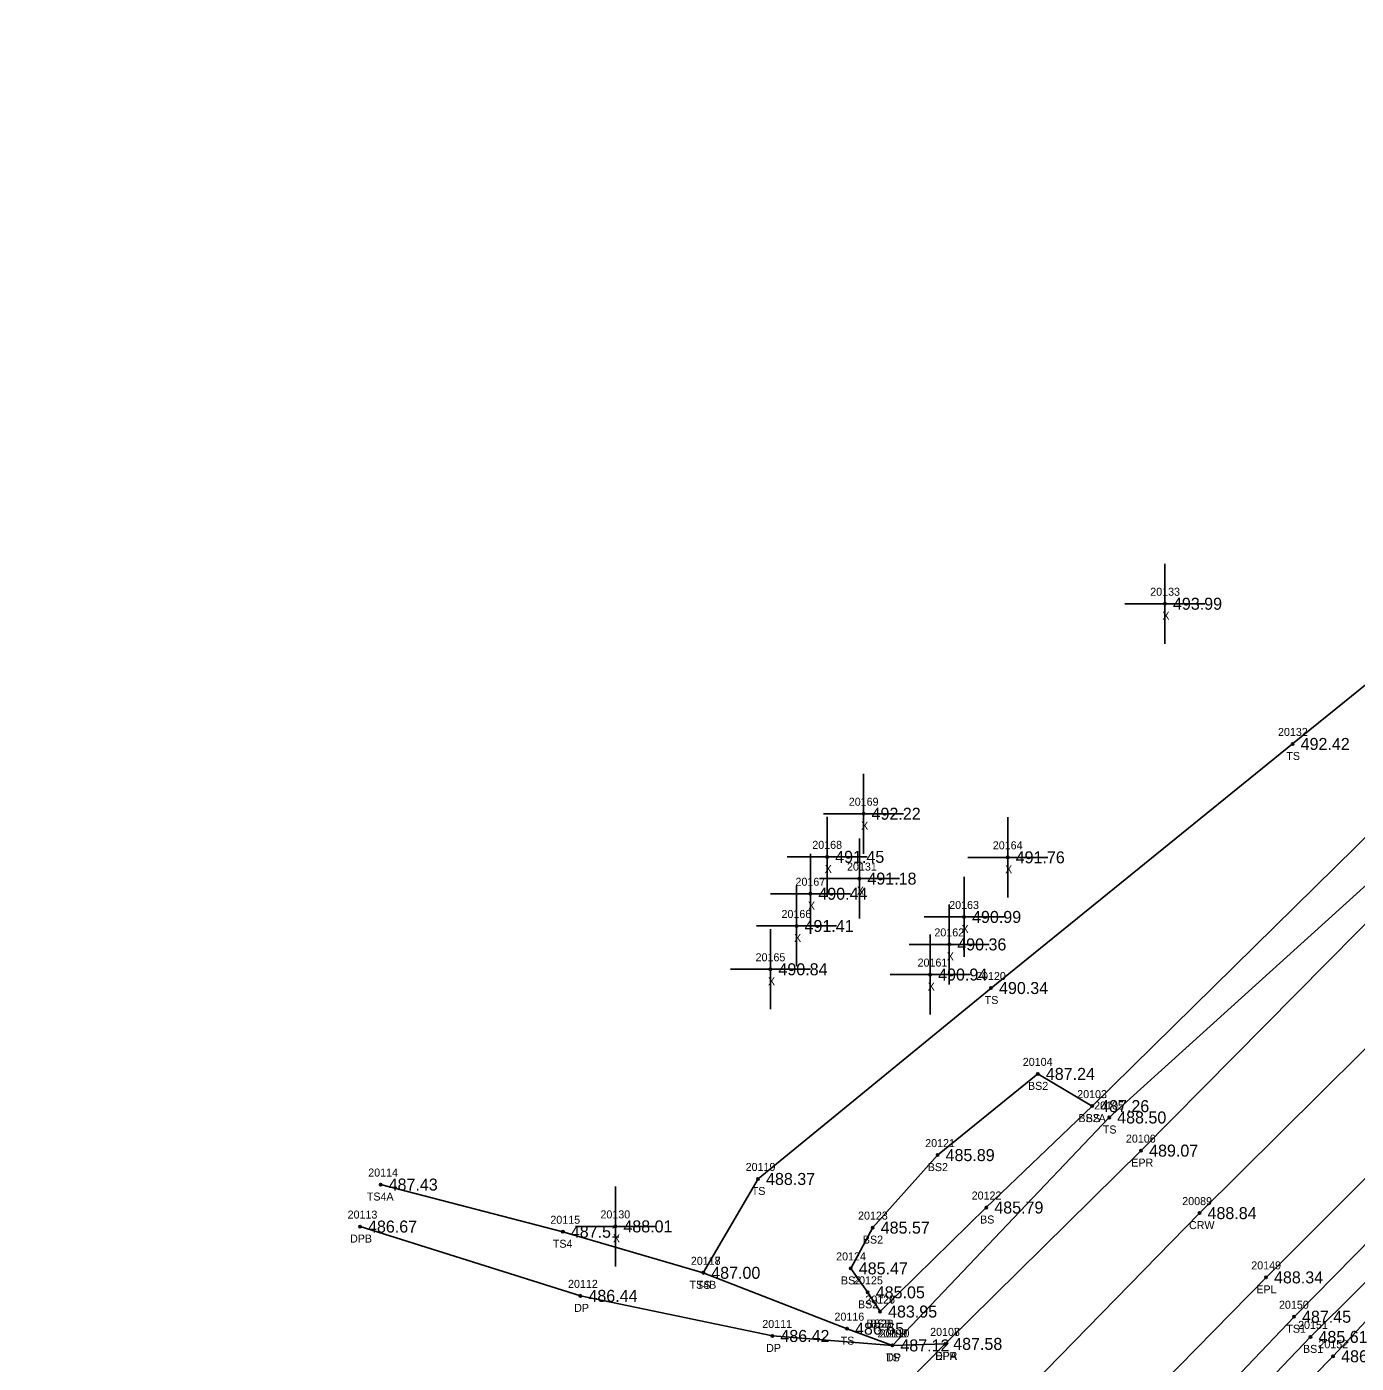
# Model space of a CAD drawing. Extents: x 1741010 to 1742139, y 749382 to 750625.
# Drawn here: x 1741801.4 to 1741967.6, y 750426.2 to 750593.3 of the extents above; entities that cross this region are included whole.
import ezdxf

# ---------------------------------------------------------------- set-up
doc = ezdxf.new("R2010")
doc.units = 0
for name, color, linetype in [('RD_DTM_BkLn1', 7, 'Continuous'), ('RD_DTM_BkLn2', 7, 'Continuous'), ('RD_DTM_BkLn_txCode', 7, 'Continuous'), ('RD_EX_Driveway', 7, 'Continuous'), ('RD_EX_Driveway_txCode', 7, 'Continuous'), ('RD_EX_Misc', 7, 'Continuous'), ('RD_EX_Misc_txCode', 7, 'Continuous'), ('RD_EX_Road', 7, 'Continuous'), ('RD_EX_Road_txCode', 7, 'Continuous'), ('RD_EX_TX_Driveway_ELEV', 7, 'Continuous'), ('RD_EX_TX_Misc_ELEV', 7, 'Continuous'), ('RD_EX_TX_Road_ELEV', 7, 'Continuous'), ('RD_HC_Survey_ELEV', 7, 'Continuous'), ('RD_HC_Survey_txCode', 7, 'Continuous'), ('RD_SMD_Locator', 7, 'Continuous')]:
    doc.layers.add(name, color=color, linetype=linetype)

msp = doc.modelspace()

# ---------------------------------------------------------------- linework, layer by layer
at = {"layer": 'RD_DTM_BkLn1'}
msp.add_lwpolyline([(1742095.1, 750579.47), (1742056.96, 750547.11), (1742019.74, 750514.22), (1741983.45, 750480.17), (1741948.01, 750445.01), (1741913.15, 750409.3), (1741879.03, 750372.99), (1741811.59, 750300.09), (1741743.65, 750226.52), (1741676.29, 750153.06), (1741642.32, 750115.53), (1741610.32, 750077.63)], dxfattribs=at)
at = {"layer": 'RD_DTM_BkLn2'}
for points in [[(1742105.6, 750567.48), (1742094.25, 750560.49), (1742091.64, 750555.7), (1742067.93, 750534.94), (1742031.73, 750501.95), (1741994.85, 750467.63), (1741959.82, 750432.06), (1741925.8, 750396.31), (1741891.25, 750362.62), (1741824.36, 750287.7), (1741756.44, 750214.6), (1741688.69, 750142.04), (1741655.55, 750103.43), (1741644.64, 750083.31), (1741626.06, 750060.3), (1741620, 750055.3), (1741614.97, 750059.12), (1741617.5, 750064.27), (1741619.23, 750067.96)], [(1742107.37, 750564.98), (1742099.21, 750558.66), (1742095.99, 750559.5), (1742095.15, 750554.39), (1742069.73, 750532.61), (1742034.06, 750499.81), (1741997.6, 750464.99), (1741961.88, 750429.54), (1741928.13, 750394.17), (1741895.34, 750359.02), (1741826.5, 750286.36), (1741758.73, 750213.29), (1741690.1, 750140.59), (1741658.36, 750099.77), (1741650.43, 750077.87), (1741632.9, 750061.59), (1741621.97, 750051.56), (1741618.99, 750048.78), (1741611.88, 750047.79)], [(1742108.6, 750563.87), (1742101.48, 750556.48), (1742102.57, 750548.5), (1742101.05, 750532.99), (1742105.06, 750513.92), (1742103.27, 750510.53), (1742100.54, 750509.6), (1742099.13, 750514.58), (1742095.78, 750530.6), (1742094.19, 750550.08), (1742071, 750531.59), (1742035.26, 750498.87), (1741998.91, 750463.73), (1741964.71, 750427.12), (1741930.26, 750392.09), (1741896.36, 750357.96), (1741828.15, 750284.74), (1741760.22, 750211.9), (1741691.37, 750138.81), (1741661.95, 750096.11), (1741655.14, 750072.69), (1741637.21, 750056.01), (1741627.61, 750046.43), (1741623.09, 750045.5)], [(1742037.14, 750559.31), (1742007.02, 750528.39), (1741970.04, 750493.22), (1741934.59, 750458.38), (1741921.36, 750445.71), (1741908.08, 750432.71)], [(1742045.12, 750555.47), (1742011.8, 750524.29), (1741973.5, 750489.25), (1741973.31, 750490.05), (1741936.72, 750456.96), (1741909.62, 750428.48), (1741903.95, 750430.57), (1741885.98, 750437.55), (1741892.83, 750449.28), (1741921.95, 750473.14), (1741959.65, 750503.64), (1742000.15, 750536.41)], [(1741934.59, 750458.38), (1741927.8, 750462.41), (1741915.27, 750452.26), (1741907.16, 750443.2), (1741904.42, 750438.1), (1741906.54, 750435.11), (1741908.08, 750432.71)], [(1741845.66, 750448.58), (1741868.43, 750442.68), (1741885.98, 750437.55)]]:
    msp.add_lwpolyline(points, dxfattribs=at)
at = {"layer": 'RD_EX_Driveway'}
msp.add_lwpolyline([(1741916.22, 750428.67), (1741909.62, 750428.48), (1741894.62, 750429.66), (1741870.63, 750434.67), (1741843.08, 750443.33)], dxfattribs=at)
at = {"layer": 'RD_EX_Misc'}
for p, q in [((1741943.69, 750516.16), (1741943.69, 750526.16)), ((1741938.69, 750521.16), (1741948.69, 750521.16)), ((1741906.02, 750489.92), (1741906.02, 750499.92)), ((1741901.02, 750494.92), (1741911.02, 750494.92)), ((1741901.47, 750484.53), (1741901.47, 750494.53)), ((1741924.03, 750484.47), (1741924.03, 750494.47)), ((1741905.5, 750481.81), (1741905.5, 750491.81)), ((1741899.37, 750479.92), (1741899.37, 750489.92)), ((1741896.47, 750489.53), (1741906.47, 750489.53)), ((1741919.03, 750489.47), (1741929.03, 750489.47)), ((1741900.5, 750486.81), (1741910.5, 750486.81)), ((1741918.58, 750477.02), (1741918.58, 750487.02)), ((1741894.37, 750484.92), (1741904.37, 750484.92)), ((1741897.64, 750475.89), (1741897.64, 750485.89)), ((1741916.73, 750473.59), (1741916.73, 750483.59)), ((1741913.58, 750482.02), (1741923.58, 750482.02)), ((1741892.64, 750480.89), (1741902.64, 750480.89)), ((1741894.38, 750470.48), (1741894.38, 750480.48)), ((1741914.34, 750469.82), (1741914.34, 750479.82)), ((1741911.73, 750478.59), (1741921.73, 750478.59)), ((1741889.38, 750475.48), (1741899.38, 750475.48)), ((1741909.34, 750474.82), (1741919.34, 750474.82)), ((1741875, 750438.35), (1741875, 750448.35)), ((1741870, 750443.35), (1741880, 750443.35))]:
    msp.add_line(p, q, dxfattribs=at)
at = {"layer": 'RD_EX_Road'}
for points in [[(1742095.24, 750593.27), (1742088.27, 750587.97), (1742078.23, 750580.89), (1742049.13, 750555.21), (1742012.94, 750522.73), (1741975.54, 750488.03), (1741940.71, 750452.82), (1741916.22, 750428.67), (1741904.72, 750416.99), (1741884.38, 750395.02), (1741870.75, 750380.27), (1741817.36, 750322.98), (1741803.89, 750307.66), (1741783.86, 750287.33), (1741735.44, 750234.07), (1741718.84, 750214.98), (1741710.25, 750205.58), (1741668.97, 750159.8), (1741635, 750122.49), (1741604.35, 750087.7), (1741600.63, 750085.47)], [(1742102.43, 750570.61), (1742093.26, 750562.71), (1742064.72, 750538.42), (1742027.92, 750505.65), (1741991.25, 750471.83), (1741956.32, 750436.98), (1741921.43, 750401.39), (1741886.79, 750364.93), (1741819.64, 750292.67), (1741751.78, 750219.01), (1741684.42, 750145.59), (1741650.98, 750108.5), (1741637.17, 750092.42), (1741621.17, 750073.94), (1741621.31, 750072.22), (1741619.24, 750070.27)]]:
    msp.add_lwpolyline(points, dxfattribs=at)
at = {"layer": 'RD_SMD_Locator'}
for centre in [(1741943.69, 750521.16), (1741959.65, 750503.64), (1741906.02, 750494.92), (1741901.47, 750489.53), (1741924.03, 750489.47), (1741905.5, 750486.81), (1741899.37, 750484.92), (1741918.58, 750482.02), (1741897.64, 750480.89), (1741916.73, 750478.59), (1741894.38, 750475.48), (1741914.34, 750474.82), (1741921.95, 750473.14), (1741927.8, 750462.41), (1741934.59, 750458.38), (1741934.59, 750458.38), (1741936.72, 750456.96), (1741940.71, 750452.82), (1741915.27, 750452.26), (1741845.66, 750448.58), (1741892.83, 750449.28), (1741921.36, 750445.71), (1741948.01, 750445.01), (1741843.08, 750443.33), (1741875, 750443.35), (1741907.16, 750443.2), (1741868.43, 750442.68), (1741904.42, 750438.1), (1741885.98, 750437.55), (1741885.98, 750437.55), (1741956.32, 750436.98), (1741870.63, 750434.67), (1741906.54, 750435.11), (1741908.08, 750432.71), (1741908.08, 750432.71), (1741959.82, 750432.06), (1741894.62, 750429.66), (1741903.95, 750430.57), (1741961.88, 750429.54), (1741909.62, 750428.48), (1741909.62, 750428.48), (1741916.22, 750428.67), (1741916.22, 750428.67), (1741964.71, 750427.12)]:
    msp.add_circle(centre, 0.15, dxfattribs=at)

# ---------------------------------------------------------------- texts
at = {"layer": 'RD_DTM_BkLn_txCode'}
for s, p in [('20132', (1741957.82, 750504.64)), ('TS', (1741958.86, 750501.64)), ('20120', (1741920.08, 750474.14)), ('TS', (1741921.16, 750471.14)), ('20104', (1741925.92, 750463.41)), ('BS2', (1741926.57, 750460.41)), ('20102', (1741932.72, 750459.38)), ('20103', (1741932.72, 750459.38)), ('20105', (1741934.84, 750457.96)), ('BS2A', (1741932.87, 750456.38)), ('BS', (1741933.81, 750456.38)), ('TS', (1741935.92, 750454.96)), ('20121', (1741913.72, 750453.26)), ('20119', (1741891.28, 750450.28)), ('BS2', (1741914.04, 750450.26)), ('20114', (1741844.11, 750449.58)), ('TS', (1741892.04, 750447.28)), ('TS4A', (1741843.93, 750446.58)), ('20122', (1741919.53, 750446.71)), ('20115', (1741866.87, 750443.68)), ('20123', (1741905.33, 750444.2)), ('BS', (1741920.58, 750443.71)), ('TS4', (1741867.18, 750440.68)), ('BS2', (1741905.93, 750441.2)), ('20124', (1741902.59, 750439.1)), ('20117', (1741884.43, 750438.55)), ('20118', (1741884.43, 750438.55)), ('TS4B', (1741884.26, 750435.55)), ('TS', (1741885.18, 750435.55)), ('BS2', (1741903.19, 750436.1)), ('20125', (1741904.71, 750436.11)), ('20126', (1741906.23, 750433.71)), ('20127', (1741906.25, 750433.71)), ('BS2', (1741905.32, 750433.11)), ('20150', (1741957.94, 750433.06)), ('20116', (1741902.38, 750431.57)), ('BS2B', (1741906.38, 750430.71)), ('BSB', (1741906.83, 750430.71)), ('20151', (1741960.33, 750430.54)), ('TS', (1741903.16, 750428.57)), ('20110', (1741908.03, 750429.48)), ('TS1', (1741958.86, 750430.06)), ('BS1', (1741960.94, 750427.54)), ('20152', (1741962.87, 750428.12)), ('TS', (1741908.83, 750426.48))]:
    msp.add_text(s, height=1, dxfattribs=at).set_placement(p)
at = {"layer": 'RD_EX_Driveway_txCode'}
for s, p in [('20113', (1741841.53, 750444.33)), ('DPB', (1741841.83, 750441.33)), ('20112', (1741869.08, 750435.67)), ('DP', (1741869.85, 750432.67)), ('20111', (1741893.36, 750430.66)), ('20109', (1741907.75, 750429.48)), ('20108', (1741914.34, 750429.67)), ('DP', (1741893.84, 750427.66)), ('DP', (1741908.84, 750426.48)), ('DPA', (1741914.95, 750426.67))]:
    msp.add_text(s, height=1, dxfattribs=at).set_placement(p)
at = {"layer": 'RD_EX_Misc_txCode'}
for s, p in [('20133', (1741941.85, 750522.16)), ('X', (1741943.37, 750519.16)), ('20169', (1741904.17, 750495.92)), ('X', (1741905.71, 750492.92)), ('20168', (1741899.61, 750490.53)), ('20164', (1741922.17, 750490.47)), ('X', (1741901.16, 750487.53)), ('20131', (1741903.95, 750487.81)), ('X', (1741923.71, 750487.47)), ('20167', (1741897.51, 750485.92)), ('X', (1741905.18, 750484.81)), ('X', (1741899.06, 750482.92)), ('20163', (1741916.72, 750483.02)), ('20166', (1741895.76, 750481.89)), ('X', (1741897.33, 750478.89)), ('20162', (1741914.87, 750479.59)), ('X', (1741918.26, 750480.02)), ('20165', (1741892.52, 750476.48)), ('20161', (1741912.77, 750475.82)), ('X', (1741916.42, 750476.59)), ('X', (1741894.07, 750473.48)), ('X', (1741914.03, 750472.82)), ('20130', (1741873.13, 750444.35)), ('X', (1741874.69, 750441.35))]:
    msp.add_text(s, height=1, dxfattribs=at).set_placement(p)
at = {"layer": 'RD_EX_Road_txCode'}
for s, p in [('20106', (1741938.81, 750453.82)), ('EPR', (1741939.48, 750450.82)), ('20149', (1741954.48, 750437.98)), ('EPL', (1741955.11, 750434.98)), ('20107', (1741914.34, 750429.67)), ('EPR', (1741914.99, 750426.67))]:
    msp.add_text(s, height=1, dxfattribs=at).set_placement(p)
at = {"layer": 'RD_EX_TX_Driveway_ELEV'}
for s, p in [('486.67', (1741844.08, 750442.58)), ('486.44', (1741871.63, 750433.92)), ('486.42', (1741895.62, 750428.91)), ('487.12', (1741910.62, 750427.73)), ('487.58', (1741917.22, 750427.92))]:
    msp.add_text(s, height=1.5, dxfattribs=at).set_placement(p)
at = {"layer": 'RD_EX_TX_Misc_ELEV'}
for s, p in [('493.99', (1741944.69, 750520.41)), ('492.42', (1741960.65, 750502.89)), ('492.22', (1741907.02, 750494.17)), ('491.45', (1741902.47, 750488.78)), ('491.76', (1741925.03, 750488.72)), ('491.18', (1741906.5, 750486.06)), ('490.44', (1741900.37, 750484.17)), ('491.41', (1741898.64, 750480.14)), ('490.99', (1741919.58, 750481.27)), ('490.36', (1741917.73, 750477.84)), ('490.84', (1741895.38, 750474.73)), ('490.94', (1741915.34, 750474.07)), ('490.34', (1741922.95, 750472.39)), ('487.24', (1741928.8, 750461.66)), ('487.26', (1741935.59, 750457.63)), ('487.26', (1741935.59, 750457.63)), ('488.50', (1741937.72, 750456.21)), ('485.89', (1741916.27, 750451.51)), ('488.37', (1741893.83, 750448.53)), ('487.43', (1741846.66, 750447.83)), ('485.79', (1741922.36, 750444.96)), ('487.51', (1741869.43, 750441.93)), ('488.01', (1741876, 750442.6)), ('485.57', (1741908.16, 750442.45)), ('487.00', (1741886.98, 750436.8)), ('487.00', (1741886.98, 750436.8)), ('485.47', (1741905.42, 750437.35)), ('485.05', (1741907.54, 750434.36)), ('483.95', (1741909.08, 750431.96)), ('483.95', (1741909.08, 750431.96)), ('486.65', (1741904.95, 750429.82)), ('487.45', (1741960.82, 750431.31)), ('485.61', (1741962.88, 750428.79)), ('487.12', (1741910.62, 750427.73)), ('486.81', (1741965.71, 750426.37))]:
    msp.add_text(s, height=1.5, dxfattribs=at).set_placement(p)
at = {"layer": 'RD_EX_TX_Road_ELEV'}
for s, p in [('489.07', (1741941.71, 750452.07)), ('488.34', (1741957.32, 750436.23)), ('487.58', (1741917.22, 750427.92))]:
    msp.add_text(s, height=1.5, dxfattribs=at).set_placement(p)
at = {"layer": 'RD_HC_Survey_ELEV'}
msp.add_text('488.84', height=1.5, dxfattribs=at).set_placement((1741949.01, 750444.26))
at = {"layer": 'RD_HC_Survey_txCode'}
for s, p in [('20089', (1741945.85, 750446.01)), ('CRW', (1741946.69, 750443.01))]:
    msp.add_text(s, height=1, dxfattribs=at).set_placement(p)

doc.saveas('drawing.dxf')
